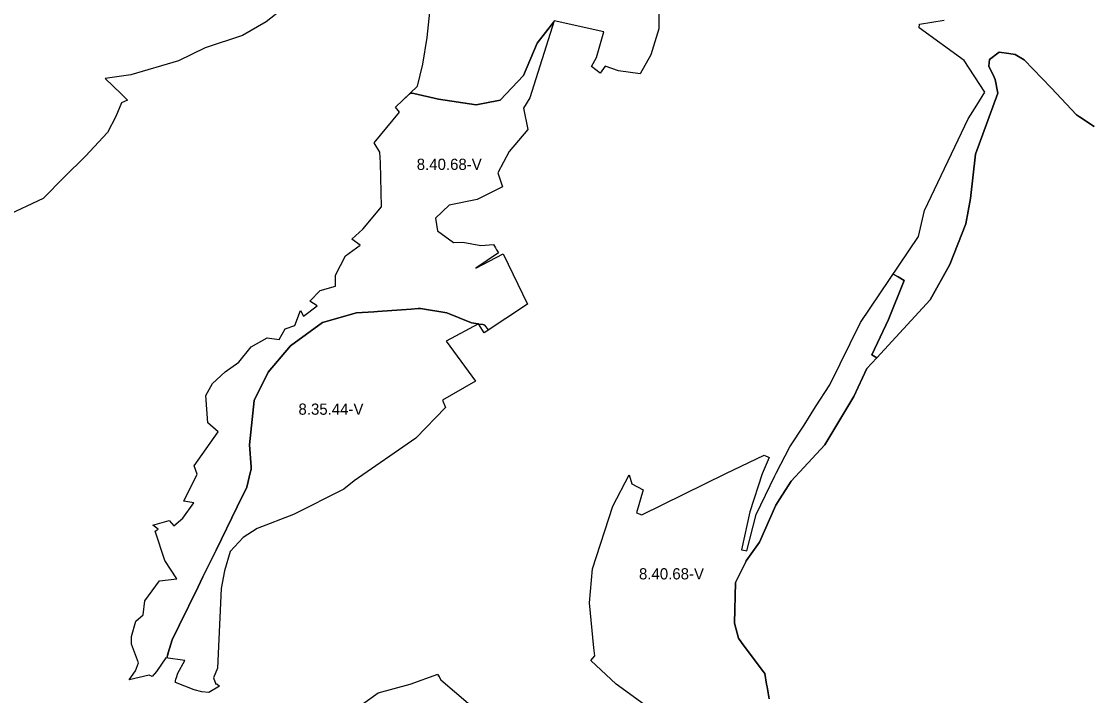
# Model space of a CAD drawing. Extents: x -547623 to -533936, y -1096714 to -1086523.
# Drawn here: x -544707 to -543752, y -1094224 to -1093623 of the extents above; entities that cross this region are included whole.
import ezdxf

# ---------------------------------------------------------------- set-up
doc = ezdxf.new("R2010")
doc.units = 0
doc.layers.add('Vrstva 27', color=7, linetype='Continuous')
doc.layers.add('Vrstva 28', color=7, linetype='Continuous')

msp = doc.modelspace()

# ---------------------------------------------------------------- linework, layer by layer
at = {"layer": 'Vrstva 28'}
for p, q in [((-544232.16, -1093623.07), (-544247, -1093642)), ((-544247, -1093642), (-544232.16, -1093623.07)), ((-544247, -1093642), (-544259, -1093671)), ((-544259, -1093671), (-544247, -1093642)), ((-543843.5, -1093656.5), (-543835, -1093650)), ((-543835, -1093650), (-543843.5, -1093656.5)), ((-543835, -1093650), (-543826.29, -1093651.2)), ((-543826.29, -1093651.2), (-543835, -1093650)), ((-543826.29, -1093651.2), (-543820.5, -1093652)), ((-543820.5, -1093652), (-543826.29, -1093651.2)), ((-543844, -1093662.5), (-543843.5, -1093656.5)), ((-543843.5, -1093656.5), (-543844, -1093662.5)), ((-543820.5, -1093652), (-543812.5, -1093657)), ((-543812.5, -1093657), (-543820.5, -1093652)), ((-543812.5, -1093657), (-543788.5, -1093682)), ((-543788.5, -1093682), (-543812.5, -1093657)), ((-543839.45, -1093672.42), (-543844, -1093662.5)), ((-543844, -1093662.5), (-543839.45, -1093672.42)), ((-544259, -1093671), (-544280, -1093693)), ((-544280, -1093693), (-544259, -1093671)), ((-543838.5, -1093674.5), (-543839.45, -1093672.42)), ((-543839.45, -1093672.42), (-543838.5, -1093674.5)), ((-543836, -1093686.5), (-543838.5, -1093674.5)), ((-543838.5, -1093674.5), (-543836, -1093686.5)), ((-544366.04, -1093692.2), (-544360.05, -1093686.51)), ((-544360.05, -1093686.51), (-544357.17, -1093683.76)), ((-544357, -1093687), (-544360.05, -1093686.51)), ((-544360.05, -1093686.51), (-544357, -1093687)), ((-544335, -1093692), (-544357, -1093687)), ((-544357, -1093687), (-544335, -1093692)), ((-543845.02, -1093711.07), (-543836, -1093686.5)), ((-543836, -1093686.5), (-543845.02, -1093711.07)), ((-543788.5, -1093682), (-543766, -1093706)), ((-543766, -1093706), (-543788.5, -1093682)), ((-544301.5, -1093697), (-544335, -1093692)), ((-544335, -1093692), (-544301.5, -1093697)), ((-544296.9, -1093696.14), (-544301.5, -1093697)), ((-544301.5, -1093697), (-544296.9, -1093696.14)), ((-544293.51, -1093695.51), (-544296.9, -1093696.14)), ((-544296.9, -1093696.14), (-544293.51, -1093695.51)), ((-544280, -1093693), (-544293.51, -1093695.51)), ((-544293.51, -1093695.51), (-544280, -1093693)), ((-543766, -1093706), (-543763.21, -1093707.8)), ((-543763.21, -1093707.8), (-543766, -1093706)), ((-543763.21, -1093707.8), (-543750, -1093716.28)), ((-543750, -1093716.28), (-543763.21, -1093707.8)), ((-543856, -1093741), (-543845.02, -1093711.07)), ((-543845.02, -1093711.07), (-543856, -1093741)), ((-543860.5, -1093780.5), (-543856, -1093741)), ((-543856, -1093741), (-543860.5, -1093780.5)), ((-543864.5, -1093803), (-543860.5, -1093780.5)), ((-543860.5, -1093780.5), (-543864.5, -1093803)), ((-543879, -1093839.5), (-543864.5, -1093803)), ((-543864.5, -1093803), (-543879, -1093839.5)), ((-543896.5, -1093871), (-543879, -1093839.5)), ((-543879, -1093839.5), (-543896.5, -1093871)), ((-543925, -1093850.5), (-543929.56, -1093847.98)), ((-543929.56, -1093847.98), (-543925, -1093850.5)), ((-543919.5, -1093853.5), (-543925, -1093850.5)), ((-543925, -1093850.5), (-543919.5, -1093853.5)), ((-543933.5, -1093888.5), (-543919.5, -1093853.5)), ((-543919.5, -1093853.5), (-543933.5, -1093888.5)), ((-543944, -1093922.5), (-543896.5, -1093871)), ((-543896.5, -1093871), (-543944, -1093922.5)), ((-544389.4, -1093881.2), (-544367.84, -1093879.68)), ((-544367.84, -1093879.68), (-544389.4, -1093881.2)), ((-544367.84, -1093879.68), (-544359.37, -1093879.09)), ((-544359.37, -1093879.09), (-544367.84, -1093879.68)), ((-544359.37, -1093879.09), (-544353.17, -1093878.65)), ((-544353.17, -1093878.65), (-544359.37, -1093879.09)), ((-544353.17, -1093878.65), (-544351, -1093878.5)), ((-544351, -1093878.5), (-544353.17, -1093878.65)), ((-544351, -1093878.5), (-544327.5, -1093882.5)), ((-544327.5, -1093882.5), (-544351, -1093878.5)), ((-544438.5, -1093891), (-544408, -1093882.5)), ((-544408, -1093882.5), (-544438.5, -1093891)), ((-544408, -1093882.5), (-544392.56, -1093881.42)), ((-544392.56, -1093881.42), (-544408, -1093882.5)), ((-544392.56, -1093881.42), (-544389.4, -1093881.2)), ((-544389.4, -1093881.2), (-544392.56, -1093881.42)), ((-544327.5, -1093882.5), (-544305.5, -1093891.5)), ((-544305.5, -1093891.5), (-544327.5, -1093882.5)), ((-543948.5, -1093920), (-543933.5, -1093888.5)), ((-543933.5, -1093888.5), (-543948.5, -1093920)), ((-544467, -1093912), (-544438.5, -1093891)), ((-544438.5, -1093891), (-544467, -1093912)), ((-544305.5, -1093891.5), (-544299.47, -1093892.4)), ((-544299.47, -1093892.4), (-544305.5, -1093891.5)), ((-544299.35, -1093892.42), (-544295.5, -1093893)), ((-544295.5, -1093893), (-544299.35, -1093892.42)), ((-544299.35, -1093892.42), (-544299.35, -1093892.42)), ((-544299.35, -1093892.42), (-544299.35, -1093892.42)), ((-544295.5, -1093893), (-544293.5, -1093893.5)), ((-544293.5, -1093893.5), (-544295.5, -1093893)), ((-544290.36, -1093897.68), (-544290.36, -1093897.68)), ((-544487, -1093935.5), (-544467, -1093912)), ((-544467, -1093912), (-544487, -1093935.5)), ((-543953, -1093932), (-543944, -1093922.5)), ((-543944, -1093922.5), (-543953, -1093932)), ((-543944, -1093922.5), (-543948.5, -1093920)), ((-543948.5, -1093920), (-543944, -1093922.5)), ((-544499.5, -1093960.5), (-544487, -1093935.5)), ((-544487, -1093935.5), (-544499.5, -1093960.5)), ((-543964.5, -1093957), (-543953, -1093932)), ((-543953, -1093932), (-543964.5, -1093957)), ((-543990.5, -1094000), (-543964.5, -1093957)), ((-543964.5, -1093957), (-543990.5, -1094000)), ((-544503.5, -1094000), (-544499.5, -1093960.5)), ((-544499.5, -1093960.5), (-544503.5, -1094000)), ((-544502.14, -1094019.87), (-544503.5, -1094000)), ((-544503.5, -1094000), (-544502.14, -1094019.87)), ((-544020.5, -1094032.5), (-543990.5, -1094000)), ((-543990.5, -1094000), (-544020.5, -1094032.5)), ((-544502.8, -1094025.21), (-544502, -1094022)), ((-544502, -1094022), (-544502.8, -1094025.21)), ((-544502, -1094022), (-544502.14, -1094019.87)), ((-544502.14, -1094019.87), (-544502, -1094022)), ((-544506, -1094038), (-544504.68, -1094032.73)), ((-544504.68, -1094032.73), (-544506, -1094038)), ((-544504.68, -1094032.73), (-544502.8, -1094025.21)), ((-544502.8, -1094025.21), (-544504.68, -1094032.73)), ((-544030.47, -1094048.38), (-544020.5, -1094032.5)), ((-544020.5, -1094032.5), (-544030.47, -1094048.38)), ((-544514.48, -1094055.35), (-544506, -1094038)), ((-544506, -1094038), (-544514.48, -1094055.35)), ((-544034, -1094054), (-544030.47, -1094048.38)), ((-544030.47, -1094048.38), (-544034, -1094054)), ((-544533.37, -1094093.98), (-544514.48, -1094055.35)), ((-544514.48, -1094055.35), (-544533.37, -1094093.98)), ((-544048.5, -1094087), (-544034, -1094054)), ((-544034, -1094054), (-544048.5, -1094087)), ((-544060.5, -1094103.5), (-544048.5, -1094087)), ((-544048.5, -1094087), (-544060.5, -1094103.5)), ((-544541.57, -1094110.75), (-544533.37, -1094093.98)), ((-544533.37, -1094093.98), (-544541.57, -1094110.75)), ((-544070, -1094123), (-544060.93, -1094104.38)), ((-544060.93, -1094104.38), (-544070, -1094123)), ((-544060.93, -1094104.38), (-544060.5, -1094103.5)), ((-544060.5, -1094103.5), (-544060.93, -1094104.38)), ((-544549.38, -1094126.72), (-544545.07, -1094117.91)), ((-544545.07, -1094117.91), (-544549.38, -1094126.72)), ((-544545.07, -1094117.91), (-544541.57, -1094110.75)), ((-544541.57, -1094110.75), (-544545.07, -1094117.91)), ((-544566.3, -1094161.33), (-544549.38, -1094126.72)), ((-544549.38, -1094126.72), (-544566.3, -1094161.33)), ((-544071, -1094159), (-544070, -1094123)), ((-544070, -1094123), (-544071, -1094159)), ((-544572.5, -1094174), (-544566.3, -1094161.33)), ((-544566.3, -1094161.33), (-544572.5, -1094174)), ((-544067.5, -1094172.5), (-544071, -1094159)), ((-544071, -1094159), (-544067.5, -1094172.5)), ((-544574.84, -1094181.7), (-544572.5, -1094174)), ((-544572.5, -1094174), (-544574.84, -1094181.7)), ((-544064.69, -1094176.27), (-544067.5, -1094172.5)), ((-544067.5, -1094172.5), (-544064.69, -1094176.27)), ((-544046.2, -1094201.05), (-544064.69, -1094176.27)), ((-544064.69, -1094176.27), (-544046.2, -1094201.05)), ((-544576.94, -1094188.87), (-544576, -1094185.5)), ((-544576, -1094185.5), (-544576.51, -1094187.31)), ((-544576, -1094185.5), (-544574.84, -1094181.7)), ((-544574.84, -1094181.7), (-544576, -1094185.5)), ((-544044, -1094204), (-544046.2, -1094201.05)), ((-544046.2, -1094201.05), (-544044, -1094204)), ((-544042.3, -1094213.54), (-544044, -1094204)), ((-544044, -1094204), (-544042.3, -1094213.54)), ((-544041.88, -1094215.92), (-544042.3, -1094213.54)), ((-544042.3, -1094213.54), (-544041.88, -1094215.92)), ((-544040, -1094226.5), (-544041.88, -1094215.92)), ((-544041.88, -1094215.92), (-544040, -1094226.5))]:
    msp.add_line(p, q, dxfattribs=at)
for points in [[(-544138.16, -1093601.33), (-544138.53, -1093629.26), (-544145.5, -1093652.33), (-544155.19, -1093669.26), (-544174.49, -1093666.83), (-544186.41, -1093662.65), (-544190.67, -1093668.66), (-544198.37, -1093662.83), (-544194.09, -1093654.8), (-544187.58, -1093631.95), (-544231.86, -1093622.13), (-544253.47, -1093690.89), (-544259.1, -1093699.96), (-544255.29, -1093719.03), (-544271.97, -1093738.72), (-544282.06, -1093757.6), (-544277.77, -1093770.15), (-544300.51, -1093781.38), (-544325.53, -1093786.51), (-544337.71, -1093798.08), (-544335.89, -1093809.47), (-544321.59, -1093819.68), (-544313.28, -1093819.6), (-544297.25, -1093822.37), (-544285.85, -1093821.61), (-544284.19, -1093824.46), (-544283.19, -1093826.23), (-544281.51, -1093828.84), (-544301.62, -1093842.5), (-544277.34, -1093829.83), (-544255.62, -1093874.7), (-544294.33, -1093900.31), (-544299.39, -1093892.36), (-544328.06, -1093907.6), (-544301.89, -1093943.46), (-544331.28, -1093960.3), (-544328.67, -1093966.87), (-544355.24, -1093994.15), (-544410.07, -1094032.13), (-544419.38, -1094039.61), (-544464.18, -1094062.37), (-544496.76, -1094074.85), (-544509.08, -1094082.72), (-544520.85, -1094095.36), (-544525.96, -1094112.59), (-544528.81, -1094128.36), (-544531.96, -1094199.25), (-544535.52, -1094207.78), (-544533.55, -1094213.53), (-544532.77, -1094213.09), (-544530.33, -1094215.42)], [(-544473.61, -1093611.03), (-544488.81, -1093622.94), (-544509.87, -1093635.1), (-544543.07, -1093646.08), (-544566.82, -1093657.81), (-544609.39, -1093670.35), (-544632.19, -1093673.54), (-544617.98, -1093687.08), (-544612.28, -1093692.94), (-544617.64, -1093695.14), (-544622.7, -1093707.3), (-544630.28, -1093721.63), (-544649.83, -1093742.67), (-544668.86, -1093761.43), (-544687.52, -1093780.56), (-544721.65, -1093796.65)], [(-544569.5, -1094210.62), (-544569.1, -1094209.13), (-544568.68, -1094207.57), (-544567.41, -1094203.82), (-544561.24, -1094192.54), (-544578.29, -1094189.92), (-544586.41, -1094202.33), (-544590.33, -1094206.79), (-544593, -1094205.41), (-544610.93, -1094209.69), (-544605.09, -1094201.64), (-544602.61, -1094194.46), (-544608.7, -1094177.77), (-544608.7, -1094170.89), (-544604.88, -1094157.39), (-544598.47, -1094151.64), (-544596.82, -1094139.09), (-544583.92, -1094121.42), (-544568.4, -1094119.62), (-544579.06, -1094103.15), (-544587.79, -1094077.12), (-544584.91, -1094075.23), (-544589.65, -1094071.86), (-544575.28, -1094067.61), (-544570.98, -1094072.22), (-544562.91, -1094065.54), (-544553.28, -1094051.83), (-544562.12, -1094050.49), (-544550.09, -1094026.37), (-544553.02, -1094019.01), (-544531.61, -1093988.62), (-544540.83, -1093980.43), (-544542.4, -1093956.05), (-544536.64, -1093945.45), (-544525.13, -1093935), (-544513.13, -1093926.3), (-544502.13, -1093912.69), (-544487.66, -1093904.72), (-544477, -1093906.19), (-544471.62, -1093896.74), (-544462.98, -1093893.78), (-544457.9, -1093880.5), (-544455.23, -1093885.34), (-544443.26, -1093876.26), (-544449.59, -1093872.1), (-544440.36, -1093862.44), (-544426.96, -1093858.82), (-544426.96, -1093848.82), (-544417.95, -1093831.69), (-544404.84, -1093822.06), (-544412.4, -1093816.75), (-544402.44, -1093807.9), (-544385.94, -1093787.93), (-544386.63, -1093748.79), (-544387.39, -1093739.31), (-544392.44, -1093730.81), (-544369.84, -1093703.59), (-544373.17, -1093698.99), (-544353.73, -1093680.49), (-544349.04, -1093660.69), (-544345.05, -1093636.88), (-544342.12, -1093608.69)], [(-544148.18, -1094234.16), (-544176.57, -1094213.45), (-544199.18, -1094192.56), (-544195.57, -1094188.27), (-544196.28, -1094181.04), (-544200.39, -1094141.05), (-544197.59, -1094110.71), (-544179.55, -1094054.7), (-544165.03, -1094027), (-544162.39, -1094034.94), (-544152.29, -1094040.4), (-544158.46, -1094060.77), (-544153.64, -1094062.5), (-544078.66, -1094025.81), (-544044.44, -1094009.29), (-544040.1, -1094011.54), (-544046.35, -1094026.08), (-544057.12, -1094059.74), (-544064.76, -1094093.78), (-544061.05, -1094094.44), (-544060, -1094094.63), (-544051.48, -1094062.27), (-544034.93, -1094027.86), (-544033.7, -1094025.42), (-544021.73, -1094001.81), (-544008.7, -1093982.5), (-543998.69, -1093966.28), (-543986.01, -1093946.54), (-543958.67, -1093890.99), (-543906.85, -1093814.42), (-543901.43, -1093791.17), (-543862.54, -1093709.63), (-543854.83, -1093697.21), (-543847.65, -1093685.64), (-543866.18, -1093657.51), (-543906.23, -1093628.33), (-543905.85, -1093625.2), (-543883.8, -1093621.66)], [(-543750, -1093716.28), (-543763.21, -1093707.8), (-543766, -1093706), (-543788.5, -1093682), (-543812.5, -1093657), (-543820.5, -1093652), (-543826.29, -1093651.2), (-543835, -1093650), (-543843.5, -1093656.5), (-543844, -1093662.5), (-543839.45, -1093672.42), (-543838.5, -1093674.5), (-543836, -1093686.5), (-543845.02, -1093711.07), (-543856, -1093741), (-543860.5, -1093780.5), (-543864.5, -1093803), (-543879, -1093839.5), (-543896.5, -1093871), (-543944, -1093922.5), (-543953, -1093932), (-543964.5, -1093957), (-543990.5, -1094000), (-544020.5, -1094032.5), (-544030.47, -1094048.38), (-544034, -1094054), (-544048.5, -1094087), (-544060.5, -1094103.5), (-544060.93, -1094104.38), (-544070, -1094123), (-544071, -1094159), (-544067.5, -1094172.5), (-544064.69, -1094176.27), (-544046.2, -1094201.05), (-544044, -1094204), (-544042.3, -1094213.54), (-544041.88, -1094215.92), (-544040, -1094226.5)], [(-544357.17, -1093683.76), (-544360.05, -1093686.51), (-544366.04, -1093692.2)], [(-544299.47, -1093892.4), (-544305.5, -1093891.5), (-544327.5, -1093882.5), (-544351, -1093878.5), (-544353.17, -1093878.65), (-544359.37, -1093879.09), (-544367.84, -1093879.68), (-544389.4, -1093881.2), (-544392.56, -1093881.42), (-544408, -1093882.5), (-544438.5, -1093891), (-544467, -1093912), (-544487, -1093935.5), (-544499.5, -1093960.5), (-544503.5, -1094000), (-544502.14, -1094019.87), (-544502, -1094022), (-544502.8, -1094025.21), (-544504.68, -1094032.73), (-544506, -1094038), (-544514.48, -1094055.35), (-544533.37, -1094093.98), (-544541.57, -1094110.75), (-544545.07, -1094117.91), (-544549.38, -1094126.72), (-544566.3, -1094161.33), (-544572.5, -1094174), (-544574.84, -1094181.7), (-544576, -1094185.5), (-544577.36, -1094190.35)], [(-544290.36, -1093897.68), (-544293.5, -1093893.5), (-544295.5, -1093893), (-544299.35, -1093892.42)], [(-544407.77, -1094234.85), (-544388.67, -1094221.11), (-544360.16, -1094213.56), (-544335.56, -1094204.63), (-544332.87, -1094209.56), (-544308.54, -1094230.45)], [(-544530.33, -1094215.42), (-544539.83, -1094220.9), (-544546.19, -1094220.38), (-544552.83, -1094218.47), (-544569.61, -1094212.01), (-544569.5, -1094210.62)], [(-544335.19, -1094206.2), (-544335.64, -1094206.31)]]:
    msp.add_lwpolyline(points, dxfattribs=at)

# ---------------------------------------------------------------- texts
at = {"layer": 'Vrstva 27'}
for s, p in [('8.40.68-V', (-544354.36, -1093755.04)), ('8.35.44-V', (-544459.85, -1093973.32)), ('8.40.68-V', (-544156.14, -1094120.14))]:
    msp.add_text(s, height=10, dxfattribs=at).set_placement(p)

doc.saveas('drawing.dxf')
